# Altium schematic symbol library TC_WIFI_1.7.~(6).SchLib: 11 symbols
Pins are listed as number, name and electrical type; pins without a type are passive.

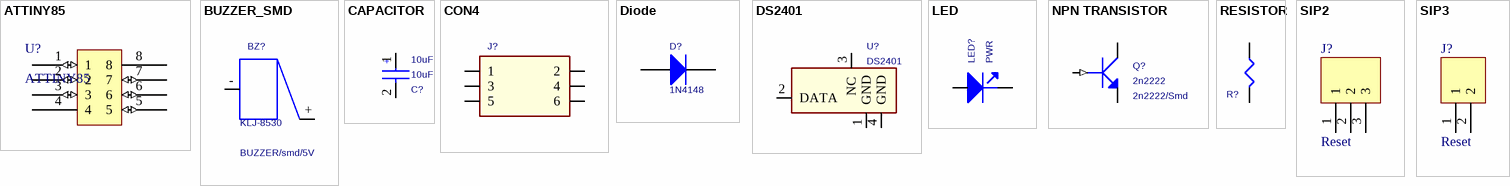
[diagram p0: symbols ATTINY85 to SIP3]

## ATTINY85
designator U?
footprint SO_8
pins: 1 (io), 2 (io), 3 (io), 4 (power), 5 (io), 6 (io), 7 (io), 8 (power)

## BUZZER_SMD
designator BZ?, comment KLJ-8530  PART: BUZZER/smd/5V
Buzzer
footprint BUZZER_SMD
pins: +, -

## CAPACITOR
designator C?, comment 10uF  PART: 10uF/Smd
Capacitor
footprint 0805_C
pins: 1 +, 2 -

## CON4
designator J?
Header 2*3 Male
footprint CON4
pins: 1, 2, 3, 4, 5, 6

## Diode
designator D?, comment 1N4148
Diode
footprint 0805-D
pins: A, K

## DS2401
designator U?
Silicon Serial Number
footprint DS2401
pins: 1 GND, 2 DATA, 3 NC, 4 GND

## LED
designator LED?, comment PWR
LED
footprint 0805-LED
pins: 1, 2

## NPN TRANSISTOR
designator Q?, comment 2n2222  PART: 2n2222/Smd
NPN Transistor
footprint 2N2222
pins: 1 (in), 2, 3

## RESISTOR
designator R?
Resistor; PART: 270K/Smd
footprint 0805_R
pins: 1, 2

## SIP2
designator J?, comment Reset
3P Male Header
footprint SIP3 M R
pins: 1, 2, 3

## SIP3
designator J?, comment Reset
3P Male Header
footprint SIP3 M R
pins: 1, 2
